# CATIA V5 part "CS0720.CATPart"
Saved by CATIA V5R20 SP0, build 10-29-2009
Part number: CS0720
Revision: 5
Definition: design
Nomenclature: CS0720
Source: made
Description: NOT SPECIFIED
Bounding box of the stored display mesh (mm): x -18.807 to 19, y -19 to 19, z -36 to 9
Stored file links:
  C:\Users\Raffaele\Desktop\3D X SITO CF\BOLEX\20-TILTED COLUMN SUPPORT\CS0720.CATPart
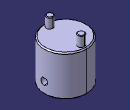
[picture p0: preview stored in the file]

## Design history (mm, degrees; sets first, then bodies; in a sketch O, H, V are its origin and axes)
Body1 "MANIFOLD_SOLID_BREP #695" (main body)
  Solid1: solid without history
